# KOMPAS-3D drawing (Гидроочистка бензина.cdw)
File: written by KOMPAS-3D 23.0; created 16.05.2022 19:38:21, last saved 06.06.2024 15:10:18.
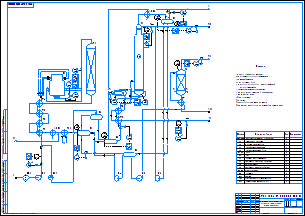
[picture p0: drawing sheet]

Sheet 1: A1, landscape

Document properties: Автор: 79870418100; Полное имя файла: G:\Учёба\Курсовое проектирование\Курсовой проект 4 курс\Дроб ГО 200\Диплом Дроб\Для публикации\Гидротчистка бензина.cdw; Литера: У

Title block, sheet 1: Наименование: Проект установки гидроочистки бензина / Схема комбинированная / принципиальная; designation: УТЭК 18.02.09.ПП.00.00.000.С3; Количество листов документа: 1; cell 10: КИПиА; Форматы листов документа: A1; stored path: C:\Users\79870\Desktop\Ахметнабиев.cdw

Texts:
  АВО1
  ХК1
  АВО2
  III
  VII
  XII
  Обознач.
  Кол.
  АВО1...АВО3
  Аппарат воздушного охлаждения
  Рефлюксная емкость
  Емкость кислой воды
  Колонна стабилизации
  Колонна отчистки воды
  Насос
  Печь
  Реактор гидроотчитки
  Сепаратор высокого давления
  Газосепаратор
  Сепаратор низкого давления
  Теплообменник
  Ребойлер
  Фильтр
  ХВ1
  Холодильник оборотной воды
  ЦК1
  Центробежный компрессор
  ПК1
  FIC
  PIC
  TIC
  LIC
  II - Свежий водородсодержащий газ
  IV - Оборотная вода
  V - Водород, сероводород, углеродный газ
  VI - Стабильный гидрогенизат
  VII - Вода после отпарки в канализацию
  VIII - Дымовые газы
  IX - Водяной пар
  Х - Азот
  XI - Сероводородный газ на факел
  XII - Жидкие углевороды на установку риформинга
  Потоки
Dimensions and other numbers on the sheet: 3; 1; 4; 7; 1-1; 1-2; 1-3; 2-4; 2-3; 2; 2-2; 2-1; 3-3; 7-1; 7-2; 7-3; 8; 8-1; 8-3; 8-2; 9-1; 9; 9-3; 9-2; 10-1; 10-2; 10; 10-3; 5-2; 5-3; 6-3; 6-2; 6; 6-1; 4-3; 4-2; 5-1; 5; 4-1; 3-2; 3-1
